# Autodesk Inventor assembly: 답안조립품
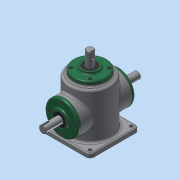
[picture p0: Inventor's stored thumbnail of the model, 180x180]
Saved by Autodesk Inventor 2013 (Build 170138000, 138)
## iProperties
Created: 2015-10
Part Number: 답안조립품
Document SubType Name: Assembly
Designer: Administrator
Author: Administrator
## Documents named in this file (14)
- C:\Users\Administrator\Desktop\451008V1005\답안조립품.iam
- C:\Users\Administrator\Desktop\451008V1005\본체.ipt
- C:\Users\Administrator\Desktop\451008V1005\커버.ipt
- C:\Users\Administrator\Desktop\451008V1005\오일실.ipt
- C:\Users\Administrator\Desktop\451008V1005\베어링 6203.ipt
- C:\Users\Administrator\Desktop\451008V1005\M4.ipt
- C:\Users\Administrator\Desktop\451008V1005\메인 축.ipt
- 메인 축.ipt
- C:\Users\Administrator\Desktop\451008V1005\키 5x5.ipt
- C:\Users\Administrator\Desktop\451008V1005\메인 베벨기어.ipt
- C:\Users\Administrator\Desktop\451008V1005\서브 축.ipt
- 서브 축.ipt
- C:\Users\Administrator\Desktop\451008V1005\키 4x4.ipt
- C:\Users\Administrator\Desktop\451008V1005\서브 베벨기어.ipt
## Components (12 placed, 1 different names)
1. M4:1
2. M4:3
3. M4:4
4. M4:5
5. M4:2
6. M4:6
7. M4:7
8. M4:8
9. M4:9
10. M4:10
11. M4:11
12. M4:12
